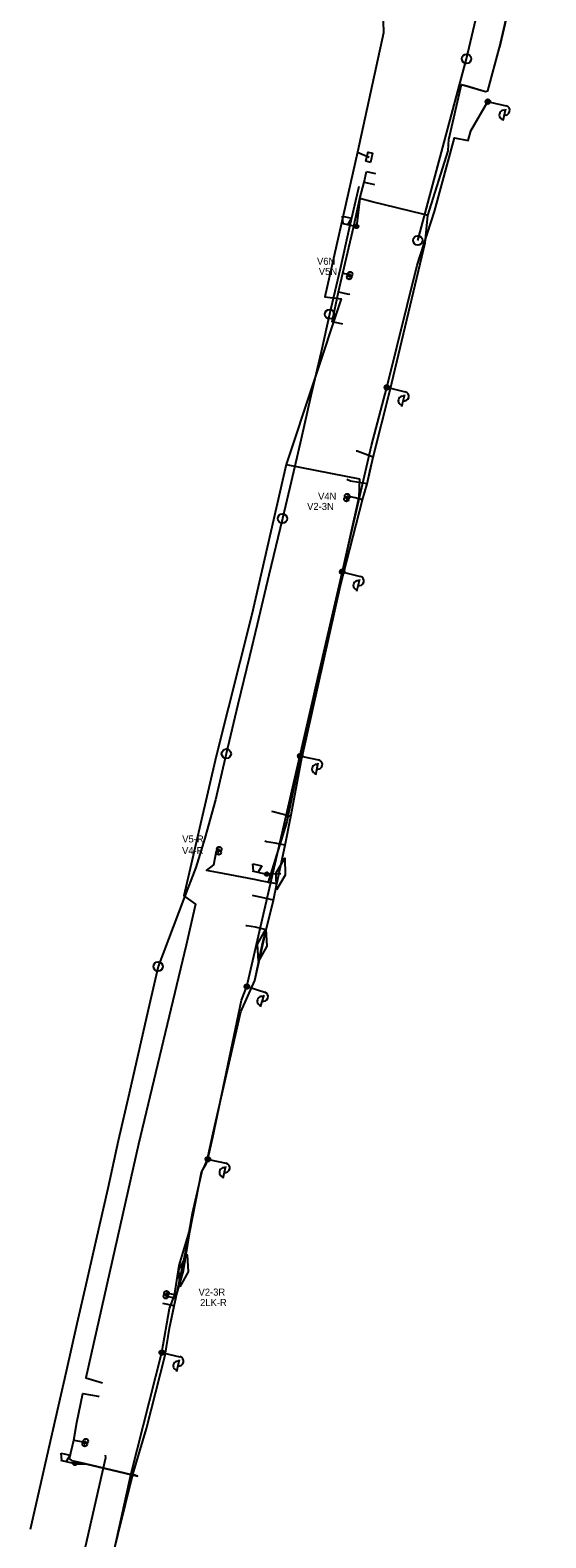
# Model space of a CAD drawing. Extents: x -748507 to -687366, y -1057342 to -1024924.
# Drawn here: x -743540.2 to -743430.1, y -1035721.9 to -1035400.5 of the extents above; entities that cross this region are included whole.
import ezdxf

# ---------------------------------------------------------------- set-up
doc = ezdxf.new("R2010")
doc.units = 0
for name, color, linetype in [('DK + TKK - SŽDC', 7, 'Continuous'), ('kanalizace ČD', 7, 'Continuous'), ('Sděl MK - SŽDC', 7, 'Continuous'), ('TK+DOK_Pha Holešovice - Kralupy', 7, 'Continuous'), ('Vedení NN - SŽDC', 7, 'Continuous')]:
    doc.layers.add(name, color=color, linetype=linetype)

msp = doc.modelspace()

# ---------------------------------------------------------------- linework, layer by layer
at = {"layer": 'DK + TKK - SŽDC'}
for p, q in [((-743472.14, -1035453.18), (-743472.04, -1035453.18)), ((-743471.96, -1035452.54), (-743471.86, -1035452.54)), ((-743472.75, -1035500.5), (-743472.65, -1035500.5)), ((-743472.62, -1035499.86), (-743472.52, -1035499.86)), ((-743500, -1035575.8), (-743499.9, -1035575.8)), ((-743499.88, -1035575.11), (-743499.78, -1035575.11)), ((-743511.28, -1035670.43), (-743511.18, -1035670.43)), ((-743511.14, -1035669.76), (-743511.04, -1035669.76)), ((-743528.39, -1035701.3), (-743528.29, -1035701.3)), ((-743528.6, -1035701.94), (-743528.5, -1035701.94))]:
    msp.add_line(p, q, dxfattribs=at)
for points in [[(-743450.19, -1035379.84), (-743449.65, -1035379.43), (-743449.77, -1035380.17), (-743450.36, -1035380.48), (-743453.08, -1035392.12), (-743453.6, -1035392.94), (-743452.51, -1035393.06), (-743449.26, -1035393.82), (-743448.28, -1035394.03), (-743447.54, -1035394.16), (-743444.4, -1035394.91), (-743444.14, -1035394.93), (-743443.62, -1035395.17), (-743442.8, -1035395.32), (-743439.9, -1035396.39), (-743438.88, -1035396.47), (-743438.2, -1035396.31), (-743440.04, -1035404.22)], [(-743455.33, -1035440.06), (-743451.01, -1035426.25), (-743450.9, -1035424.96), (-743450.86, -1035423.82), (-743448.12, -1035412.11), (-743447.02, -1035412.39), (-743443.97, -1035413.34), (-743443, -1035413.65), (-743442.53, -1035413.45), (-743440.04, -1035404.22)], [(-743473.45, -1035452.34), (-743471.1, -1035442.36), (-743469.8, -1035436.46), (-743468.9, -1035432.98), (-743468.39, -1035430.69)], [(-743468.39, -1035430.69), (-743466.87, -1035431.01), (-743466.49, -1035431.1)], [(-743468.9, -1035432.98), (-743466.96, -1035433.39), (-743466.67, -1035433.47)], [(-743455.33, -1035440.06), (-743456.42, -1035439.78), (-743467.19, -1035437.17), (-743469.8, -1035436.46)], [(-743466.96, -1035491.57), (-743463.38, -1035477.18), (-743455.87, -1035445.85), (-743455.33, -1035440.06)], [(-743473.45, -1035463.21), (-743473.74, -1035463.12), (-743475.77, -1035462.71), (-743474.41, -1035456.31), (-743473.45, -1035452.34)], [(-743473.45, -1035452.34), (-743472.39, -1035452.55), (-743471.91, -1035452.54)], [(-743472.39, -1035452.55), (-743472.09, -1035453.18)], [(-743474.41, -1035456.31), (-743472.53, -1035456.74), (-743471.99, -1035456.79)], [(-743466.96, -1035491.57), (-743470.39, -1035490.29), (-743470.6, -1035490.26)], [(-743468.28, -1035497.25), (-743467.67, -1035494.64), (-743466.96, -1035491.57)], [(-743467.67, -1035494.64), (-743467.89, -1035494.59)], [(-743482.27, -1035556.05), (-743473.93, -1035518.93), (-743469.27, -1035500.64), (-743468.28, -1035497.25)], [(-743468.28, -1035497.25), (-743471.79, -1035496.65), (-743472.59, -1035496.34)], [(-743472.7, -1035500.5), (-743471.86, -1035500.03), (-743472.57, -1035499.86)], [(-743469.27, -1035500.64), (-743470.85, -1035500.25), (-743471.86, -1035500.03)], [(-743487.52, -1035582.5), (-743485.74, -1035574.25), (-743484.54, -1035568.18), (-743482.27, -1035556.05)], [(-743484.54, -1035568.18), (-743486.68, -1035567.59), (-743488.35, -1035567.17), (-743488.62, -1035567.09)], [(-743487.52, -1035582.5), (-743490.65, -1035581.91), (-743492.34, -1035581.57), (-743500.19, -1035580.1), (-743502.59, -1035579.64), (-743501.01, -1035578.49), (-743500.41, -1035575.48)], [(-743499.83, -1035575.11), (-743500.41, -1035575.48), (-743499.95, -1035575.8)], [(-743485.74, -1035574.25), (-743487.88, -1035573.87), (-743489.77, -1035573.54), (-743490.14, -1035573.45)], [(-743489.86, -1035592.34), (-743488.27, -1035586), (-743487.52, -1035582.5)], [(-743488.27, -1035586), (-743490.74, -1035585.41), (-743492.48, -1035585.06), (-743492.74, -1035585.03)], [(-743489.86, -1035592.34), (-743492.08, -1035591.73), (-743493.96, -1035591.46), (-743494.17, -1035591.44)], [(-743508.99, -1035670.2), (-743506.14, -1035656.66), (-743503.65, -1035643.95), (-743502.59, -1035642.14), (-743501.12, -1035635.57), (-743495.24, -1035609.79), (-743492.27, -1035603.09), (-743489.86, -1035592.34)], [(-743515.36, -1035698.59), (-743511.35, -1035682.96), (-743510.47, -1035677.25), (-743509.46, -1035672.44)], [(-743509.46, -1035672.44), (-743511.91, -1035671.93)], [(-743509.13, -1035670.88), (-743511.23, -1035670.43)], [(-743508.99, -1035670.2), (-743511.09, -1035669.76)], [(-743509.46, -1035672.44), (-743509.13, -1035670.88), (-743508.99, -1035670.2)], [(-743531.78, -1035705.01), (-743530.91, -1035701.08), (-743530.22, -1035697.32), (-743528.94, -1035691.17), (-743525.69, -1035691.72), (-743525.49, -1035691.81)], [(-743530.91, -1035701.08), (-743528.88, -1035701.47)], [(-743528.88, -1035701.47), (-743528.34, -1035701.3)], [(-743528.88, -1035701.47), (-743528.55, -1035701.94)], [(-743518.3, -1035708.39), (-743515.36, -1035698.59)], [(-743524.2, -1035704.27), (-743524.11, -1035704.84), (-743532.95, -1035743.56)], [(-743517.31, -1035708.76), (-743528.41, -1035706.12), (-743531.22, -1035705.51), (-743531.78, -1035705.01)]]:
    msp.add_lwpolyline(points, dxfattribs=at)
for centre in [(-743472.09, -1035453.18), (-743471.91, -1035452.54), (-743472.7, -1035500.5), (-743472.57, -1035499.86), (-743499.95, -1035575.8), (-743499.83, -1035575.11), (-743511.09, -1035669.76), (-743511.23, -1035670.43), (-743528.55, -1035701.94), (-743528.34, -1035701.3)]:
    msp.add_circle(centre, 0.5, dxfattribs=at)
at = {"layer": 'kanalizace ČD'}
for points in [[(-743457.46, -1035445.36), (-743447.04, -1035406.64), (-743438.36, -1035369.74), (-743430.12, -1035371.18)], [(-743470.06, -1035433.87), (-743472.12, -1035442.78), (-743474.05, -1035451.45), (-743476.29, -1035461.1), (-743478.1, -1035469.14), (-743480.27, -1035478.46), (-743482.37, -1035487.67), (-743484.5, -1035496.85), (-743486.36, -1035504.65), (-743489.24, -1035516.73), (-743491.72, -1035527.23), (-743493.39, -1035534.02), (-743495.86, -1035544.28), (-743498.33, -1035554.77), (-743500.61, -1035564.62), (-743502.95, -1035572.78), (-743504.87, -1035579.01), (-743507.48, -1035585.85), (-743512.9, -1035600.13), (-743514.98, -1035609.39), (-743519.1, -1035627.23), (-743521.38, -1035637.26), (-743523.61, -1035647.45), (-743526.15, -1035658.64), (-743528.34, -1035668), (-743530.22, -1035676.28), (-743532.49, -1035686.49), (-743534.79, -1035696.39), (-743536.25, -1035702.93), (-743538.38, -1035712.03), (-743540.21, -1035720.15)]]:
    msp.add_lwpolyline(points, dxfattribs=at)
for centre in [(-743447.04, -1035406.64), (-743457.46, -1035445.36), (-743476.29, -1035461.1), (-743486.36, -1035504.65), (-743498.33, -1035554.77), (-743512.9, -1035600.13)]:
    msp.add_circle(centre, 1, dxfattribs=at)
at = {"layer": 'Sděl MK - SŽDC'}
for p, q in [((-743473.37, -1035441.75), (-743473.53, -1035440.18)), ((-743473.53, -1035440.18), (-743471.58, -1035440.62)), ((-743471.58, -1035440.62), (-743472.4, -1035441.98)), ((-743473.66, -1035441.69), (-743470.94, -1035442.31)), ((-743470.52, -1035442.77), (-743470.89, -1035442.18)), ((-743470.19, -1035442.55), (-743470.55, -1035441.97)), ((-743492.53, -1035579.82), (-743492.68, -1035578.25)), ((-743492.68, -1035578.25), (-743490.73, -1035578.69)), ((-743490.73, -1035578.69), (-743491.55, -1035580.04)), ((-743492.82, -1035579.76), (-743490.09, -1035580.37)), ((-743489.68, -1035580.84), (-743490.05, -1035580.25)), ((-743489.34, -1035580.62), (-743489.71, -1035580.04)), ((-743533.46, -1035705.42), (-743533.61, -1035703.85)), ((-743533.61, -1035703.85), (-743531.66, -1035704.29)), ((-743531.66, -1035704.29), (-743532.48, -1035705.65)), ((-743533.75, -1035705.36), (-743531.03, -1035705.97)), ((-743530.61, -1035706.44), (-743530.98, -1035705.85)), ((-743530.28, -1035706.22), (-743530.64, -1035705.64))]:
    msp.add_line(p, q, dxfattribs=at)
for points in [[(-743484.54, -1035568.18), (-743482.27, -1035556.05), (-743473.93, -1035518.93), (-743469.27, -1035500.64), (-743468.28, -1035497.25), (-743467.67, -1035494.64), (-743466.96, -1035491.57), (-743463.38, -1035477.18), (-743455.87, -1035445.85), (-743455.33, -1035440.06), (-743451.01, -1035426.25), (-743450.9, -1035424.96), (-743450.86, -1035423.82), (-743448.12, -1035412.11), (-743443, -1035413.65), (-743442.53, -1035413.45), (-743440.04, -1035404.22), (-743438.2, -1035396.31)], [(-743455.33, -1035440.06), (-743456.42, -1035439.78), (-743467.19, -1035437.17), (-743469.8, -1035436.46), (-743470.54, -1035442.37)], [(-743487.63, -1035583.78), (-743487.7, -1035580.14), (-743485.84, -1035577.01), (-743485.77, -1035580.65), (-743487.63, -1035583.78)], [(-743486.73, -1035580.39), (-743489.7, -1035580.44)], [(-743491.45, -1035598.98), (-743491.64, -1035595.35), (-743489.88, -1035592.16), (-743489.69, -1035595.8), (-743491.45, -1035598.98)], [(-743506.14, -1035656.66), (-743503.65, -1035643.95), (-743502.59, -1035642.14), (-743501.12, -1035635.57), (-743495.24, -1035609.79), (-743492.27, -1035603.09), (-743490.67, -1035595.57), (-743489.86, -1035592.34)], [(-743524.56, -1035733.68), (-743518.3, -1035708.39), (-743515.36, -1035698.59), (-743511.35, -1035682.96), (-743510.47, -1035677.25), (-743509.46, -1035672.44), (-743509.13, -1035670.88), (-743508.99, -1035670.2), (-743507.46, -1035664.98), (-743506.14, -1035656.66)], [(-743508.23, -1035668.4), (-743508.44, -1035664.76), (-743506.69, -1035661.57), (-743506.48, -1035665.2), (-743508.23, -1035668.4)], [(-743530.52, -1035706.13), (-743528.41, -1035706.12), (-743517.31, -1035708.76), (-743518.3, -1035708.39)]]:
    msp.add_lwpolyline(points, dxfattribs=at)
for centre in [(-743470.54, -1035442.37), (-743470.54, -1035442.37), (-743489.7, -1035580.44), (-743489.7, -1035580.44), (-743530.63, -1035706.04), (-743530.63, -1035706.04)]:
    msp.add_circle(centre, 0.401, dxfattribs=at)
at = {"layer": 'TK+DOK_Pha Holešovice - Kralupy'}
for points in [[(-743524.56, -1035733.68), (-743518.3, -1035708.39), (-743515.36, -1035698.59), (-743511.35, -1035682.96), (-743510.47, -1035677.25), (-743508.99, -1035670.2), (-743506.14, -1035656.66), (-743503.65, -1035643.95), (-743502.59, -1035642.14), (-743501.12, -1035635.57), (-743495.24, -1035609.79), (-743492.27, -1035603.09), (-743489.86, -1035592.34), (-743488.27, -1035586), (-743487.52, -1035582.5), (-743485.74, -1035574.25), (-743484.54, -1035568.18), (-743482.27, -1035556.05), (-743473.93, -1035518.93), (-743469.27, -1035500.64), (-743468.28, -1035497.25), (-743466.96, -1035491.57), (-743463.38, -1035477.18), (-743455.87, -1035445.85), (-743455.33, -1035440.06), (-743451.01, -1035426.25), (-743450.9, -1035424.96), (-743450.86, -1035423.82), (-743448.12, -1035412.11), (-743447.02, -1035412.39), (-743443.97, -1035413.34), (-743443, -1035413.65), (-743442.53, -1035413.45), (-743440.04, -1035404.22), (-743438.2, -1035396.31)], [(-743510.47, -1035677.25), (-743508.99, -1035670.2), (-743506.14, -1035656.66), (-743503.65, -1035643.95), (-743502.59, -1035642.14), (-743501.12, -1035635.57), (-743495.24, -1035609.79), (-743492.27, -1035603.09), (-743489.86, -1035592.34), (-743488.27, -1035586), (-743487.52, -1035582.5), (-743485.74, -1035574.25), (-743484.54, -1035568.18), (-743482.27, -1035556.05), (-743473.93, -1035518.93), (-743469.27, -1035500.64), (-743468.28, -1035497.25), (-743466.96, -1035491.57), (-743463.38, -1035477.18), (-743455.87, -1035445.85), (-743455.33, -1035440.06), (-743451.01, -1035426.25), (-743450.9, -1035424.96), (-743450.86, -1035423.82), (-743448.12, -1035412.11), (-743447.02, -1035412.39), (-743443.97, -1035413.34), (-743443, -1035413.65), (-743442.53, -1035413.45), (-743440.04, -1035404.22), (-743438.2, -1035396.31)], [(-743533.09, -1035772.08), (-743526.18, -1035744.45), (-743524.82, -1035739.72), (-743524.56, -1035733.68), (-743518.3, -1035708.39), (-743515.36, -1035698.59), (-743511.35, -1035682.96), (-743510.47, -1035677.25)]]:
    msp.add_lwpolyline(points, dxfattribs=at)
at = {"layer": 'Vedení NN - SŽDC'}
for p, q in [((-743442.88, -1035415.46), (-743442.37, -1035416.27)), ((-743442.55, -1035415.29), (-743442.08, -1035416.04)), ((-743442.02, -1035415.9), (-743438.61, -1035416.68)), ((-743438.77, -1035417.36), (-743439.34, -1035419.9)), ((-743464.41, -1035476.36), (-743463.91, -1035477.17)), ((-743464.07, -1035476.19), (-743463.61, -1035476.94)), ((-743463.55, -1035476.81), (-743460.15, -1035477.62)), ((-743460.31, -1035478.3), (-743460.92, -1035480.83)), ((-743473.96, -1035515.66), (-743473.48, -1035516.48)), ((-743473.62, -1035515.5), (-743473.17, -1035516.26)), ((-743473.11, -1035516.12), (-743469.72, -1035516.99)), ((-743469.9, -1035517.67), (-743470.54, -1035520.19)), ((-743482.92, -1035554.95), (-743482.4, -1035555.75)), ((-743482.58, -1035554.77), (-743482.1, -1035555.51)), ((-743482.05, -1035555.37), (-743478.63, -1035556.1)), ((-743478.77, -1035556.79), (-743479.31, -1035559.33)), ((-743494.29, -1035604.04), (-743493.84, -1035604.89)), ((-743493.94, -1035603.9), (-743493.53, -1035604.68)), ((-743493.46, -1035604.55), (-743490.12, -1035605.6)), ((-743490.33, -1035606.27), (-743491.12, -1035608.75)), ((-743502.64, -1035640.88), (-743502.13, -1035641.69)), ((-743502.31, -1035640.71), (-743501.84, -1035641.45)), ((-743501.78, -1035641.32), (-743498.37, -1035642.08)), ((-743498.52, -1035642.77), (-743499.09, -1035645.3)), ((-743512.49, -1035682.08), (-743511.98, -1035682.89)), ((-743512.16, -1035681.91), (-743511.69, -1035682.66)), ((-743511.63, -1035682.52), (-743508.22, -1035683.3)), ((-743508.38, -1035683.98), (-743508.95, -1035686.52))]:
    msp.add_line(p, q, dxfattribs=at)
for points in [[(-743491.57, -1035324.41), (-743480.24, -1035326.91), (-743474.56, -1035328.06), (-743473.43, -1035330.06), (-743467.99, -1035332.08), (-743465.75, -1035331.97), (-743464.96, -1035332), (-743462.67, -1035333), (-743459.86, -1035333.71), (-743457.19, -1035334.43), (-743453.08, -1035335.2), (-743454.32, -1035342.1), (-743456.59, -1035352.92), (-743461.64, -1035372.17), (-743464.46, -1035385.84), (-743463.96, -1035389.24), (-743464.93, -1035396.25), (-743464.8, -1035401.1), (-743470.35, -1035426.52), (-743467.81, -1035427.64)], [(-743525.62, -1035739.77), (-743518.62, -1035708.21), (-743512.12, -1035682.41), (-743510.45, -1035673.06), (-743509.36, -1035670.28), (-743508.38, -1035663.85), (-743506.27, -1035656.76), (-743505.56, -1035652.68), (-743503.49, -1035643.76), (-743502.27, -1035641.21), (-743501.2, -1035636.49), (-743495.11, -1035607.3), (-743493.94, -1035604.4), (-743467.31, -1035489.05), (-743464.04, -1035476.69), (-743457.6, -1035450.61), (-743453.91, -1035439.17), (-743449.63, -1035423.53), (-743446.71, -1035424.06), (-743446.16, -1035422.03), (-743442.51, -1035415.79)], [(-743470.35, -1035426.52), (-743477.27, -1035457.38), (-743473.83, -1035457.84), (-743485.59, -1035493.1), (-743469.91, -1035496.17)], [(-743467.55, -1035428.73), (-743468.52, -1035428.5), (-743468.07, -1035426.55), (-743467.1, -1035426.78), (-743467.55, -1035428.73)], [(-743485.59, -1035493.1), (-743492.91, -1035525.08), (-743500.49, -1035555.28), (-743507.43, -1035585.05), (-743504.93, -1035586.86), (-743506.88, -1035595.6), (-743517.11, -1035637.98), (-743528.3, -1035687.83), (-743524.75, -1035688.9)], [(-743469.91, -1035496.17), (-743470.05, -1035500.11), (-743473.6, -1035516), (-743479.38, -1035540.91), (-743482.54, -1035555.27), (-743485.4, -1035569.27), (-743489.49, -1035582.38)]]:
    msp.add_lwpolyline(points, dxfattribs=at)
for centre in [(-743442.51, -1035415.79), (-743442.51, -1035415.79), (-743464.04, -1035476.69), (-743464.04, -1035476.69), (-743473.6, -1035516), (-743473.6, -1035516), (-743482.54, -1035555.27), (-743482.54, -1035555.27), (-743493.94, -1035604.4), (-743493.94, -1035604.4), (-743502.27, -1035641.21), (-743502.27, -1035641.21), (-743512.12, -1035682.41), (-743512.12, -1035682.41)]:
    msp.add_circle(centre, 0.5, dxfattribs=at)
for centre, start, end in [((-743439.07, -1035418.63), 76.473, 257.8781), ((-743438.83, -1035417.65), 257.1755, 77.1755), ((-743460.63, -1035479.56), 75.8176, 257.2227), ((-743460.38, -1035478.59), 256.5202, 76.5202), ((-743470.23, -1035518.92), 75.0035, 256.4086), ((-743469.97, -1035517.96), 255.7061, 75.7061), ((-743478.83, -1035557.08), 258.0218, 78.0218), ((-743479.05, -1035558.05), 77.3193, 258.7244), ((-743490.74, -1035607.51), 71.8118, 253.217), ((-743490.43, -1035606.56), 252.5144, 72.5144), ((-743498.82, -1035644.03), 76.6855, 258.0907), ((-743498.58, -1035643.06), 257.3881, 77.3881), ((-743508.68, -1035685.25), 76.4531, 257.8582), ((-743508.44, -1035684.27), 257.1556, 77.1556)]:
    msp.add_arc(centre, 1, start, end, dxfattribs=at)

# ---------------------------------------------------------------- texts
at = {"layer": 'DK + TKK - SŽDC'}
for s, p in [('V6N', (-743478.97, -1035450.56)), ('V5N', (-743478.59, -1035452.71)), ('V2-3N', (-743481.08, -1035502.81)), ('V4N', (-743478.74, -1035500.66)), ('V5-R', (-743507.74, -1035573.69)), ('V4-R', (-743507.77, -1035576.18)), ('V2-3R', (-743504.26, -1035670.28)), ('2LK-R', (-743503.93, -1035672.51))]:
    msp.add_text(s, height=1.5, dxfattribs=at).set_placement(p)

doc.saveas('drawing.dxf')
